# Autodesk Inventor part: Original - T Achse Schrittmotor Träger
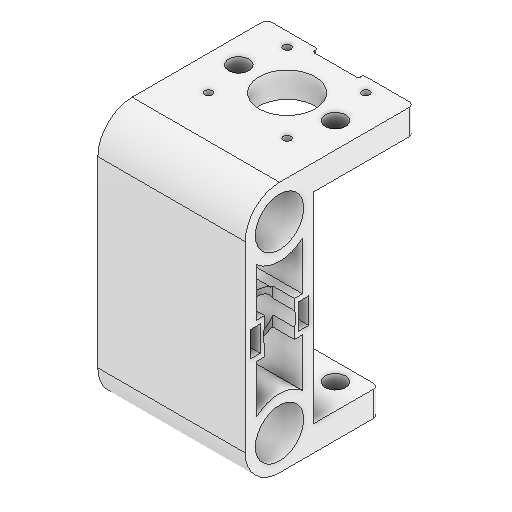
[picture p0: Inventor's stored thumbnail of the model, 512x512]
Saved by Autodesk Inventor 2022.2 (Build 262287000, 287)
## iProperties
Created: 2024-09
Part Number: Original - T Achse Schrittmotor Träger
Material: Generico
Document SubType Name: Modeling
Designer: 18907419
Density: 1 g/cm^3
Appearance: Default
Author: 18907419
Revision Number: ANY
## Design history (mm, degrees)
feature "Schnitt-Linear austragen9"
node "Solido1"
